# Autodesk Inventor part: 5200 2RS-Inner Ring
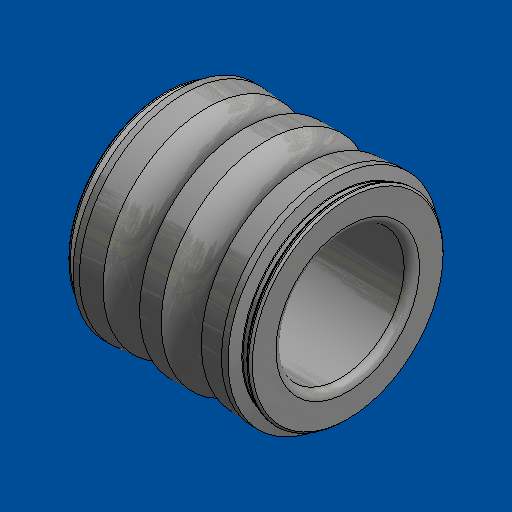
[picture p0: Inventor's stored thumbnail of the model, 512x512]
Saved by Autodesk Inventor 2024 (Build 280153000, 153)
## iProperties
Part Number: 5200 2RS-Inner Ring
Material: Generic
Document SubType Name: Modeling
Designer: amoles
Appearance: Default
Author: amoles
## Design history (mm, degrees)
feature "5200 2RS-Inner Ring"
body "Solid1"
